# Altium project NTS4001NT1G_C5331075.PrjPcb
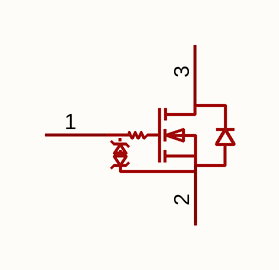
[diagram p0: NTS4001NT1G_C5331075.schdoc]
1 sheet, 1 parts. Net scope: global (net labels, ports and power ports of the same name join across sheets).

## Sheet NTS4001NT1G_C5331075.schdoc
size 127 x 101 mm

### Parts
Q?  nts4001nt1g_c5331075  [SOT-323-3_L2.0-W1.3-P1.30-LS2.1-BR]  (value not drawn)

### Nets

Not connected (* = marked no-connect by the designer): Q? 1(G) 2(S) 3(D)

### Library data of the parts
Q? = nts4001nt1g_c5331075: 数量:1个N沟道;漏源电压(Vdss):30V;连续漏极电流(Id):300mA;导通电阻(RDS(on)):1Ω@10V;耗散功率(Pd):313W;阈值电压(Vgs(th)):1.6V;; Manufacturer: MSKSEMI(美森科); AddInBom: yes; ModelId: 59529c0d6fc749f28f2d0659e12986b4; ModelName: SOT-323-3_L2.0-W1.3-H1.0-LS2.1-P1.30; ModelTransform: 78.74,82.677,0,90,0,0,0.0005,0,0; Number: 1个N沟道; Drain to Source Voltage: 30V; Current - Continuous Drain(Id): 300mA; RDS(on): 1Ω@10V; Pd - Power Dissipation: 313W; Gate Threshold Voltage (Vgs(th)): 1.6V; Input Capacitance(Ciss): 23pF; Reverse Transfer Capacitance (Crss@Vds): 10pF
